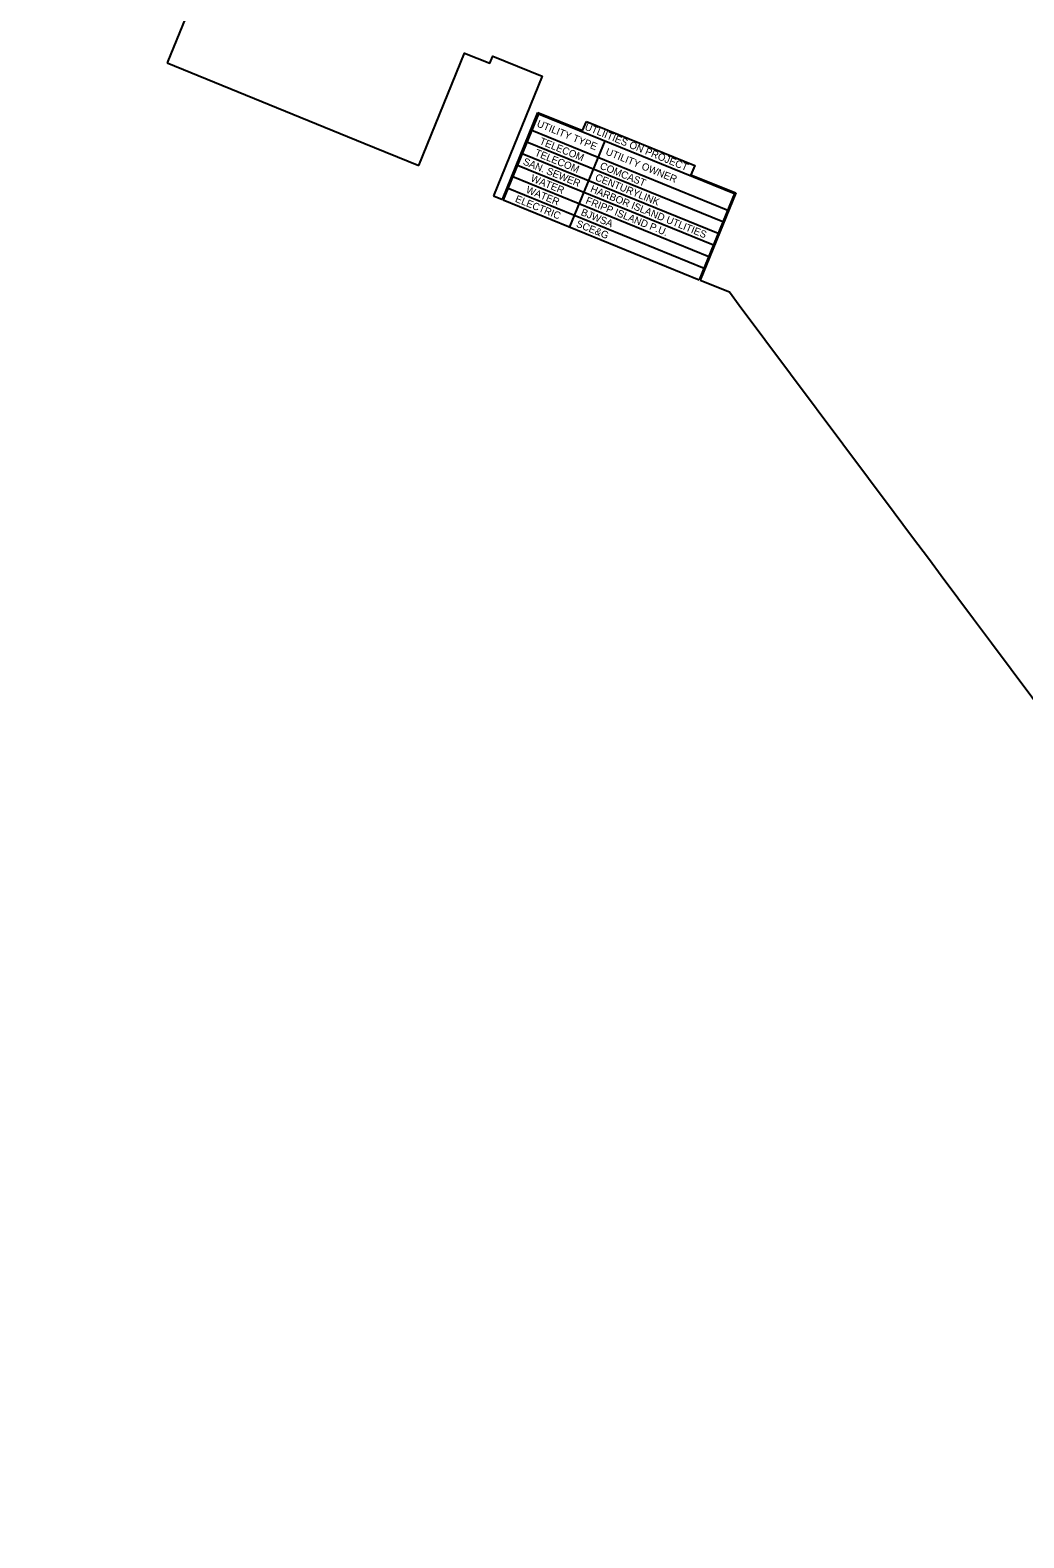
# Model space of a CAD drawing. Extents: x 2162629 to 2176228, y 202467 to 210920.
# Drawn here: x 2170156 to 2171185, y 205819 to 207382 of the extents above; entities that cross this region are included whole.
import ezdxf

# ---------------------------------------------------------------- set-up
doc = ezdxf.new("R2010")
doc.units = 0
doc.layers.add('RD_SHT_ShtClip', color=7, linetype='Continuous')
doc.layers.add('RD_SHT_TX', color=7, linetype='Continuous')

msp = doc.modelspace()

# ---------------------------------------------------------------- linework, layer by layer
at = {"layer": 'RD_SHT_ShtClip'}
for p, q in [((2170644.8, 207206.3), (2170681.6, 207296.5)), ((2170681.6, 207296.5), (2170727.9, 207277.7)), ((2170727.9, 207277.7), (2170731.8, 207287.1)), ((2170840.1, 207231.9), (2170886.5, 207213.1)), ((2170635.5, 207210.1), (2170644.8, 207206.3)), ((2170886.5, 207213.1), (2170849.7, 207122.9)), ((2170849.7, 207122.9), (2170880.1, 207110.5))]:
    msp.add_line(p, q, dxfattribs=at)
for points in [[(2170155.7, 207405.5), (2170178.1, 207460.6), (2170319.9, 207402.9), (2170297.5, 207347.8)], [(2170558.3, 207241.6), (2170605.7, 207358.1), (2170631.8, 207347.5), (2170634.9, 207355), (2170686.1, 207334.1), (2170635.5, 207210.1)], [(2170297.5, 207347.8), (2170501.2, 207264.8), (2170558.3, 207241.6)], [(2170731.8, 207287.1), (2170844, 207241.4), (2170840.1, 207231.9)], [(2170880.1, 207110.5), (2170890.2, 207096.9), (2171050.5, 206882.1)], [(2171050.5, 206882.1), (2171068.7, 206857.8), (2171087.1, 206833.2), (2171099.4, 206816.6), (2171116.5, 206793.7), (2171132.8, 206771.9), (2171143.3, 206757.9), (2171151.5, 206746.8)], [(2171151.5, 206746.8), (2171275.8, 206580.4), (2171456.7, 206338), (2171661, 206064.3), (2171785.3, 205897.8), (2171843.8, 205819.5), (2171890.3, 205854.2), (2171915.1, 205872.6)]]:
    msp.add_lwpolyline(points, dxfattribs=at)
at = {"layer": 'RD_SHT_TX'}
for p, q in [((2170682.1, 207295.2), (2170645.8, 207205.9)), ((2170682.1, 207295.2), (2170885.2, 207212.5)), ((2170670.3, 207266.1), (2170873.3, 207183.4)), ((2170675.2, 207278.1), (2170878.2, 207195.4)), ((2170750.9, 207267.2), (2170714.5, 207177.9)), ((2170665.4, 207254), (2170868.4, 207171.3)), ((2170660.5, 207242), (2170863.5, 207159.3)), ((2170650.7, 207218), (2170853.7, 207135.3)), ((2170655.6, 207230), (2170858.6, 207147.3)), ((2170645.8, 207205.9), (2170848.8, 207123.2)), ((2170885.2, 207212.5), (2170848.8, 207123.2))]:
    msp.add_line(p, q, dxfattribs=at)

# ---------------------------------------------------------------- texts
for s, p in [('UTILITY TYPE', (2170679.8, 207282.2)), ('UTLIITIES ON PROJECT', (2170729.5, 207278.9)), ('TELECOM', (2170682.6, 207264)), ('SAN. SEWER', (2170665.5, 207242.9)), ('TELECOM', (2170677.7, 207252)), ('UTILITY OWNER', (2170751.1, 207253.1)), ('WATER', (2170673.5, 207225.6)), ('CENTURYLINK', (2170740.2, 207226.5)), ('COMCAST', (2170745.1, 207238.5)), ('WATER', (2170668.6, 207213.6)), ('HARBOR ISLAND UTLITIES', (2170735.3, 207214.5)), ('ELECTRIC', (2170657.4, 207204.2)), ('FRIPP ISLAND P.U.', (2170730.4, 207202.5)), ('SCE&G', (2170720.6, 207178.4)), ('BJWSA', (2170725.5, 207190.4))]:
    msp.add_text(s, height=7.5, rotation=337.8388, dxfattribs=at).set_placement(p)

doc.saveas('drawing.dxf')
